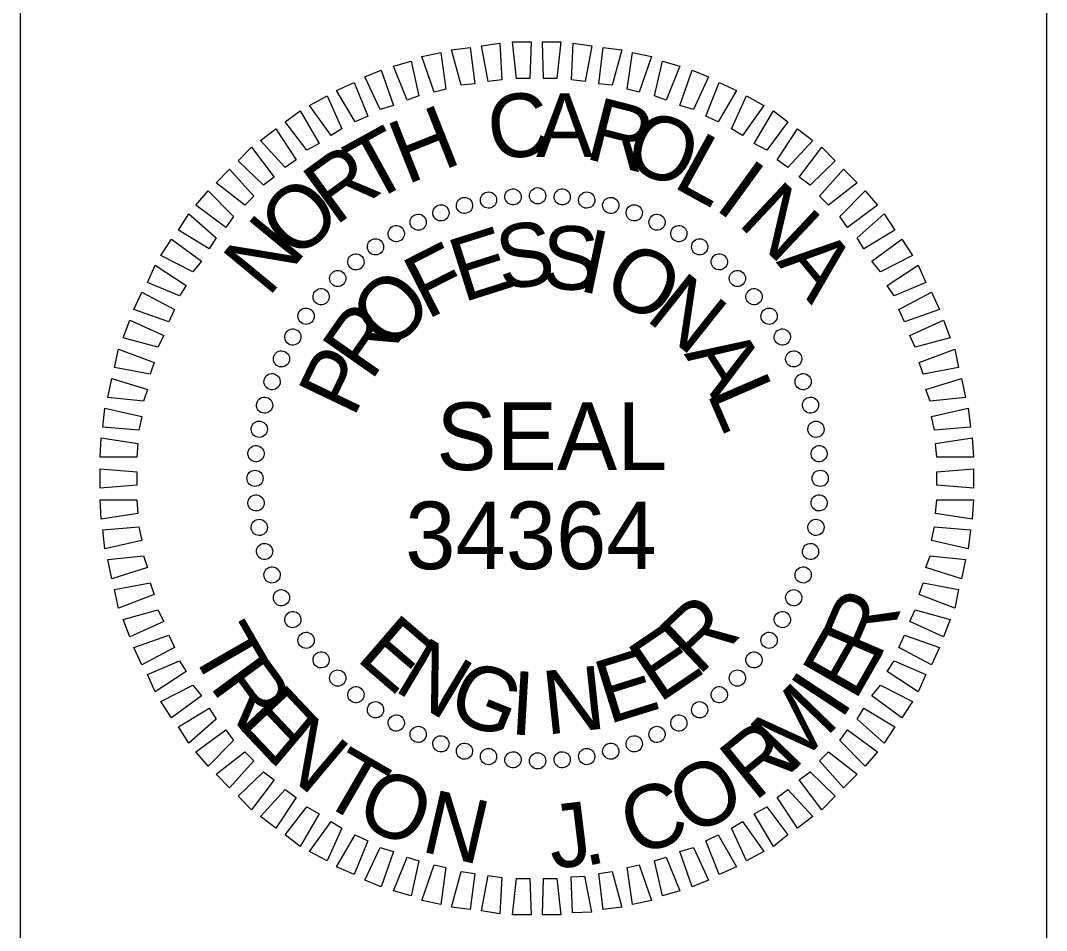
# Model space of a CAD drawing. Extents: x 2.6 to 3.27, y 0.03 to 1.77.
# Drawn here: x 2.6042 to 2.7708, y 1.2034 to 1.3512 of the extents above; entities that cross this region are included whole.
import ezdxf

# ---------------------------------------------------------------- set-up
doc = ezdxf.new("R2010")
doc.units = 0
for name, color, linetype in [('Draft_RDY_Construction_Class_Element', 7, 'Continuous'), ('Old_Level_2', 7, 'Continuous'), ('Sheet_Plan_CELL', 7, 'Continuous')]:
    doc.layers.add(name, color=color, linetype=linetype)

msp = doc.modelspace()

# ---------------------------------------------------------------- linework, layer by layer
at = {"layer": 'Draft_RDY_Construction_Class_Element'}
for p, q in [((2.60416, 0.0625), (2.60416, 1.77083)), ((2.77078, 1.77083), (2.77078, 0.0625))]:
    msp.add_line(p, q, dxfattribs=at)
at = {"layer": 'Old_Level_2'}
for p, q in [((2.68002, 1.32201), (2.68002, 1.32201)), ((2.68397, 1.32256), (2.68397, 1.32256)), ((2.68799, 1.32276), (2.68799, 1.32276)), ((2.69202, 1.32256), (2.69202, 1.32256)), ((2.69595, 1.32201), (2.69595, 1.32201)), ((2.67225, 1.32001), (2.67225, 1.32001)), ((2.67609, 1.32121), (2.67609, 1.32121)), ((2.69988, 1.32121), (2.69988, 1.32121)), ((2.70372, 1.32001), (2.70372, 1.32001)), ((2.66859, 1.31846), (2.66859, 1.31846)), ((2.7074, 1.31846), (2.7074, 1.31846)), ((2.66503, 1.3166), (2.66503, 1.3166)), ((2.71096, 1.3166), (2.71096, 1.3166)), ((2.66165, 1.31442), (2.66165, 1.31442)), ((2.71434, 1.31442), (2.71434, 1.31442)), ((2.65844, 1.31202), (2.65844, 1.31202)), ((2.71755, 1.31202), (2.71755, 1.31202)), ((2.6555, 1.30927), (2.6555, 1.30927)), ((2.72045, 1.30927), (2.72045, 1.30927)), ((2.65275, 1.30637), (2.65275, 1.30637)), ((2.7232, 1.30637), (2.7232, 1.30637)), ((2.65037, 1.30316), (2.65037, 1.30316)), ((2.7256, 1.30316), (2.7256, 1.30316)), ((2.64819, 1.29978), (2.64819, 1.29978)), ((2.72778, 1.29978), (2.72778, 1.29978)), ((2.64636, 1.2962), (2.64636, 1.2962)), ((2.72964, 1.2962), (2.72964, 1.2962)), ((2.64481, 1.29254), (2.64481, 1.29254)), ((2.73119, 1.29254), (2.73119, 1.29254)), ((2.64361, 1.2887), (2.64361, 1.2887)), ((2.73239, 1.2887), (2.73239, 1.2887)), ((2.64278, 1.28477), (2.64278, 1.28477)), ((2.73319, 1.28477), (2.73319, 1.28477)), ((2.64223, 1.28084), (2.64223, 1.28084)), ((2.73374, 1.28084), (2.73374, 1.28084)), ((2.64206, 1.27681), (2.64206, 1.27681)), ((2.73393, 1.27681), (2.73393, 1.27681)), ((2.64223, 1.27279), (2.64223, 1.27279)), ((2.73374, 1.27279), (2.73374, 1.27279)), ((2.64278, 1.26884), (2.64278, 1.26884)), ((2.73319, 1.26884), (2.73319, 1.26884)), ((2.64361, 1.26492), (2.64361, 1.26492)), ((2.73239, 1.26492), (2.73239, 1.26492)), ((2.64481, 1.26108), (2.64481, 1.26108)), ((2.73119, 1.26108), (2.73119, 1.26108)), ((2.64636, 1.25741), (2.64636, 1.25741)), ((2.72964, 1.25741), (2.72964, 1.25741)), ((2.64819, 1.25383), (2.64819, 1.25383)), ((2.72778, 1.25383), (2.72778, 1.25383)), ((2.65037, 1.25047), (2.65037, 1.25047)), ((2.7256, 1.25047), (2.7256, 1.25047)), ((2.65275, 1.24727), (2.65275, 1.24727)), ((2.7232, 1.24727), (2.7232, 1.24727)), ((2.6555, 1.24432), (2.6555, 1.24432)), ((2.72045, 1.24432), (2.72045, 1.24432)), ((2.65844, 1.24157), (2.65844, 1.24157)), ((2.71755, 1.24157), (2.71755, 1.24157)), ((2.66165, 1.23919), (2.66165, 1.23919)), ((2.71434, 1.23919), (2.71434, 1.23919)), ((2.66503, 1.23699), (2.66503, 1.23699)), ((2.71096, 1.23699), (2.71096, 1.23699)), ((2.66859, 1.23518), (2.66859, 1.23518)), ((2.7074, 1.23518), (2.7074, 1.23518)), ((2.67225, 1.23363), (2.67225, 1.23363)), ((2.70372, 1.23363), (2.70372, 1.23363)), ((2.67609, 1.23243), (2.67609, 1.23243)), ((2.68002, 1.2316), (2.68002, 1.2316)), ((2.69595, 1.2316), (2.69595, 1.2316)), ((2.69988, 1.23243), (2.69988, 1.23243)), ((2.68397, 1.23105), (2.68397, 1.23105)), ((2.68799, 1.23088), (2.68799, 1.23088)), ((2.69202, 1.23105), (2.69202, 1.23105))]:
    msp.add_line(p, q, dxfattribs=at)
for points in [[(2.67572, 1.34069), (2.67417, 1.34645), (2.67719, 1.3468), (2.67793, 1.34095)], [(2.68013, 1.3413), (2.67902, 1.34708), (2.68203, 1.34754), (2.68231, 1.34159)], [(2.68469, 1.34178), (2.68406, 1.34774), (2.68707, 1.34774), (2.68689, 1.34178)], [(2.68908, 1.34178), (2.68892, 1.34774), (2.69191, 1.34774), (2.69128, 1.34178)], [(2.69366, 1.34159), (2.69392, 1.34754), (2.69695, 1.34708), (2.69586, 1.3413)], [(2.69807, 1.34095), (2.69879, 1.3468), (2.70182, 1.34645), (2.70025, 1.34069)], [(2.67134, 1.33958), (2.66933, 1.34534), (2.67243, 1.34599), (2.67326, 1.34004)], [(2.70271, 1.34004), (2.70356, 1.34599), (2.70666, 1.34534), (2.70465, 1.33958)], [(2.66255, 1.33674), (2.66008, 1.34204), (2.66274, 1.34313), (2.66475, 1.3374)], [(2.66695, 1.33829), (2.66475, 1.34379), (2.66759, 1.3446), (2.66885, 1.33895)], [(2.70712, 1.33895), (2.70841, 1.3446), (2.71122, 1.34379), (2.70904, 1.33829)], [(2.71122, 1.3374), (2.71325, 1.34313), (2.71589, 1.34204), (2.71343, 1.33674)], [(2.65851, 1.33473), (2.6555, 1.33984), (2.65836, 1.34115), (2.66054, 1.33565)], [(2.71545, 1.33565), (2.71764, 1.34115), (2.72045, 1.33984), (2.71746, 1.33473)], [(2.6546, 1.33255), (2.65111, 1.3374), (2.65395, 1.33895), (2.65635, 1.33364)], [(2.71964, 1.33364), (2.72204, 1.33895), (2.72486, 1.3374), (2.72139, 1.33255)], [(2.65065, 1.33015), (2.64716, 1.33473), (2.64956, 1.33655), (2.65266, 1.33124)], [(2.72331, 1.33124), (2.72643, 1.33655), (2.72879, 1.33473), (2.72534, 1.33015)], [(2.64716, 1.32732), (2.64315, 1.3317), (2.64561, 1.33364), (2.64891, 1.3286)], [(2.72706, 1.3286), (2.73036, 1.33364), (2.73282, 1.3317), (2.72879, 1.32732)], [(2.64361, 1.32448), (2.63951, 1.32841), (2.64169, 1.33061), (2.64535, 1.32577)], [(2.73064, 1.32577), (2.73428, 1.33061), (2.73649, 1.32841), (2.73239, 1.32448)], [(2.6406, 1.32121), (2.63593, 1.32485), (2.63811, 1.32705), (2.64206, 1.32265)], [(2.73393, 1.32265), (2.73784, 1.32705), (2.74004, 1.32485), (2.7354, 1.32121)], [(2.63748, 1.31761), (2.63263, 1.32121), (2.63464, 1.32356), (2.63876, 1.31935)], [(2.73723, 1.31935), (2.74133, 1.32356), (2.74334, 1.32121), (2.73849, 1.31761)], [(2.63481, 1.31414), (2.6298, 1.31717), (2.63152, 1.31981), (2.63593, 1.31588)], [(2.74004, 1.31588), (2.74443, 1.31981), (2.74617, 1.31717), (2.74113, 1.31414)], [(2.63217, 1.31039), (2.62696, 1.31303), (2.62868, 1.31571), (2.63353, 1.31213)], [(2.74242, 1.31213), (2.74729, 1.31571), (2.74903, 1.31303), (2.74382, 1.31039)], [(2.62997, 1.30646), (2.62478, 1.30866), (2.62604, 1.31148), (2.63108, 1.30818)], [(2.74491, 1.30818), (2.74993, 1.31148), (2.75121, 1.30866), (2.74602, 1.30646)], [(2.62823, 1.30225), (2.62257, 1.30428), (2.62384, 1.30709), (2.62916, 1.30428)], [(2.74683, 1.30428), (2.75213, 1.30709), (2.75342, 1.30428), (2.74772, 1.30225)], [(2.62648, 1.29812), (2.62083, 1.29967), (2.62192, 1.30253), (2.62742, 1.30004)], [(2.74857, 1.30004), (2.75405, 1.30253), (2.75516, 1.29967), (2.74947, 1.29812)], [(2.62521, 1.29374), (2.61945, 1.29483), (2.62009, 1.29784), (2.62587, 1.29564)], [(2.75012, 1.29564), (2.75588, 1.29784), (2.75652, 1.29483), (2.75076, 1.29374)], [(2.62412, 1.28935), (2.61834, 1.28999), (2.619, 1.29308), (2.62478, 1.29127)], [(2.75121, 1.29127), (2.75697, 1.29308), (2.75763, 1.28999), (2.75187, 1.28935)], [(2.62338, 1.28468), (2.61753, 1.28514), (2.61788, 1.28824), (2.62384, 1.28689)], [(2.75213, 1.28689), (2.75807, 1.28824), (2.75846, 1.28514), (2.75259, 1.28468)], [(2.62303, 1.2803), (2.61708, 1.2803), (2.61725, 1.2834), (2.62323, 1.28248)], [(2.75276, 1.28248), (2.75872, 1.2834), (2.75892, 1.2803), (2.75296, 1.2803)], [(2.62303, 1.27572), (2.61708, 1.27526), (2.61708, 1.27836), (2.62303, 1.2779)], [(2.75296, 1.2779), (2.75892, 1.27836), (2.75892, 1.27526), (2.75296, 1.27572)], [(2.62323, 1.27113), (2.61725, 1.27022), (2.61708, 1.27334), (2.62303, 1.27334)], [(2.75296, 1.27334), (2.75892, 1.27334), (2.75872, 1.27022), (2.75276, 1.27113)], [(2.62384, 1.26675), (2.61788, 1.26537), (2.61753, 1.26849), (2.62338, 1.26895)], [(2.75259, 1.26895), (2.75846, 1.26849), (2.75807, 1.26537), (2.75213, 1.26675)], [(2.62478, 1.26236), (2.619, 1.26051), (2.61834, 1.26363), (2.62412, 1.26426)], [(2.75187, 1.26426), (2.75763, 1.26363), (2.75697, 1.26051), (2.75121, 1.26236)], [(2.62587, 1.25796), (2.62009, 1.25577), (2.61945, 1.25879), (2.62521, 1.25988)], [(2.75076, 1.25988), (2.75652, 1.25879), (2.75588, 1.25577), (2.75012, 1.25796)], [(2.62742, 1.25357), (2.62192, 1.25111), (2.62083, 1.25392), (2.62648, 1.25547)], [(2.74947, 1.25547), (2.75516, 1.25392), (2.75405, 1.25111), (2.74857, 1.25357)], [(2.62916, 1.24936), (2.62384, 1.24652), (2.62257, 1.24936), (2.62823, 1.25137)], [(2.74772, 1.25137), (2.75342, 1.24936), (2.75213, 1.24652), (2.74683, 1.24936)], [(2.63108, 1.24543), (2.62604, 1.24214), (2.62478, 1.24497), (2.62997, 1.24718)], [(2.74602, 1.24718), (2.75121, 1.24497), (2.74993, 1.24214), (2.74491, 1.24543)], [(2.63353, 1.24148), (2.62868, 1.23793), (2.62696, 1.24057), (2.63217, 1.24323)], [(2.74382, 1.24323), (2.74903, 1.24057), (2.74729, 1.23793), (2.74242, 1.24148)], [(2.63593, 1.23773), (2.63152, 1.2338), (2.6298, 1.23644), (2.63481, 1.23948)], [(2.74113, 1.23948), (2.74617, 1.23644), (2.74443, 1.2338), (2.74004, 1.23773)], [(2.63876, 1.23424), (2.63464, 1.23005), (2.63263, 1.23243), (2.63748, 1.23599)], [(2.73849, 1.23599), (2.74334, 1.23243), (2.74133, 1.23005), (2.73723, 1.23424)], [(2.64206, 1.23097), (2.63811, 1.22658), (2.63593, 1.22879), (2.6406, 1.23243)], [(2.7354, 1.23243), (2.74004, 1.22879), (2.73784, 1.22658), (2.73393, 1.23097)], [(2.64535, 1.22785), (2.64169, 1.223), (2.63951, 1.22521), (2.64361, 1.22913)], [(2.73239, 1.22913), (2.73649, 1.22521), (2.73428, 1.223), (2.73064, 1.22785)], [(2.64891, 1.22501), (2.64561, 1.21999), (2.64315, 1.22191), (2.64716, 1.2263)], [(2.72879, 1.2263), (2.73282, 1.22191), (2.73036, 1.21999), (2.72706, 1.22501)], [(2.65266, 1.22235), (2.64956, 1.21705), (2.64716, 1.2189), (2.65065, 1.22346)], [(2.72534, 1.22346), (2.72879, 1.2189), (2.72643, 1.21705), (2.72331, 1.22235)], [(2.65635, 1.21999), (2.65395, 1.21469), (2.65111, 1.21624), (2.6546, 1.22108)], [(2.72139, 1.22108), (2.72486, 1.21624), (2.72204, 1.21469), (2.71964, 1.21999)], [(2.66054, 1.21796), (2.65836, 1.21249), (2.6555, 1.21375), (2.65851, 1.2189)], [(2.71746, 1.2189), (2.72045, 1.21375), (2.71764, 1.21249), (2.71545, 1.21796)], [(2.66475, 1.21624), (2.66274, 1.21046), (2.66008, 1.21157), (2.66255, 1.21687)], [(2.71343, 1.21687), (2.71589, 1.21157), (2.71325, 1.21046), (2.71122, 1.21624)], [(2.66885, 1.21469), (2.66759, 1.209), (2.66475, 1.20983), (2.66695, 1.2153)], [(2.70904, 1.2153), (2.71122, 1.20983), (2.70841, 1.209), (2.70712, 1.21469)], [(2.67326, 1.2136), (2.67243, 1.20762), (2.66933, 1.20828), (2.67134, 1.21404)], [(2.70465, 1.21404), (2.70666, 1.20828), (2.70356, 1.20762), (2.70271, 1.2136)], [(2.67793, 1.21266), (2.67719, 1.20681), (2.67417, 1.20716), (2.67572, 1.21295)], [(2.68231, 1.21201), (2.68203, 1.20607), (2.67902, 1.20655), (2.68013, 1.21231)], [(2.68689, 1.21185), (2.68707, 1.2059), (2.68406, 1.2059), (2.68469, 1.21185)], [(2.69128, 1.21185), (2.69191, 1.2059), (2.68892, 1.2059), (2.68908, 1.21185)], [(2.69577, 1.2122), (2.69687, 1.20636), (2.69383, 1.20627), (2.69357, 1.21212)], [(2.70025, 1.21295), (2.70182, 1.20716), (2.69879, 1.20681), (2.69807, 1.21266)]]:
    msp.add_lwpolyline(points, close=True, dxfattribs=at)
for centre, major_axis in [((2.68017, 1.32204), (-0.00023, 0.0013)), ((2.68414, 1.32256), (-0.00011, 0.00131)), ((2.68814, 1.32274), (0, 0.00132)), ((2.69214, 1.32256), (0.00011, 0.00131)), ((2.69611, 1.32204), (0.00023, 0.0013)), ((2.67244, 1.31997), (-0.00045, 0.00124)), ((2.67626, 1.32117), (-0.00034, 0.00127)), ((2.70001, 1.32117), (0.00034, 0.00127)), ((2.70383, 1.31997), (0.00045, 0.00124)), ((2.66874, 1.31844), (-0.00056, 0.00119)), ((2.70753, 1.31844), (0.00056, 0.00119)), ((2.66519, 1.31659), (-0.00066, 0.00114)), ((2.71108, 1.31659), (0.00066, 0.00114)), ((2.66181, 1.31444), (-0.00076, 0.00108)), ((2.71446, 1.31444), (0.00076, 0.00108)), ((2.65863, 1.312), (-0.00085, 0.00101)), ((2.71764, 1.312), (0.00085, 0.00101)), ((2.65568, 1.3093), (-0.000932, 0.000932)), ((2.72059, 1.3093), (0.000932, 0.000932)), ((2.65298, 1.30634), (-0.00101, 0.00085)), ((2.72329, 1.30634), (0.00101, 0.00085)), ((2.65054, 1.30317), (-0.00108, 0.00076)), ((2.72573, 1.30317), (0.00108, 0.00076)), ((2.64839, 1.29979), (-0.00114, 0.00066)), ((2.72788, 1.29979), (0.00114, 0.00066)), ((2.64654, 1.29624), (-0.00119, 0.00056)), ((2.72973, 1.29624), (0.00119, 0.00056)), ((2.64501, 1.29254), (-0.00124, 0.00045)), ((2.73126, 1.29254), (0.00124, 0.00045)), ((2.6438, 1.28872), (-0.00127, 0.00034)), ((2.73247, 1.28872), (0.00127, 0.00034)), ((2.64294, 1.28481), (-0.0013, 0.00023)), ((2.73334, 1.28481), (0.0013, 0.00023)), ((2.64241, 1.28084), (-0.00131, 0.00011)), ((2.73386, 1.28084), (0.00131, 0.00011)), ((2.64224, 1.27684), (-0.00132, 0)), ((2.73403, 1.27684), (0.00132, 0)), ((2.64241, 1.27284), (-0.00131, -0.00011)), ((2.73386, 1.27284), (0.00131, -0.00011)), ((2.64294, 1.26887), (-0.0013, -0.00023)), ((2.73334, 1.26887), (0.0013, -0.00023)), ((2.6438, 1.26496), (-0.00127, -0.00034)), ((2.73247, 1.26496), (0.00127, -0.00034)), ((2.64501, 1.26114), (-0.00124, -0.00045)), ((2.73126, 1.26114), (0.00124, -0.00045)), ((2.64654, 1.25744), (-0.00119, -0.00056)), ((2.72973, 1.25744), (0.00119, -0.00056)), ((2.64839, 1.25389), (-0.00114, -0.00066)), ((2.72788, 1.25389), (0.00114, -0.00066)), ((2.65054, 1.25052), (-0.00108, -0.00076)), ((2.72573, 1.25052), (0.00108, -0.00076)), ((2.65298, 1.24734), (-0.00101, -0.00085)), ((2.72329, 1.24734), (0.00101, -0.00085)), ((2.65568, 1.24439), (-0.000932, -0.000932)), ((2.72059, 1.24439), (0.000932, -0.000932)), ((2.65863, 1.24168), (-0.00085, -0.00101)), ((2.71764, 1.24168), (0.00085, -0.00101)), ((2.66181, 1.23924), (-0.00076, -0.00108)), ((2.71446, 1.23924), (0.00076, -0.00108)), ((2.66519, 1.23709), (-0.00066, -0.00114)), ((2.71108, 1.23709), (0.00066, -0.00114)), ((2.66874, 1.23524), (-0.00056, -0.00119)), ((2.70753, 1.23524), (0.00056, -0.00119)), ((2.67244, 1.23371), (-0.00045, -0.00124)), ((2.70383, 1.23371), (0.00045, -0.00124)), ((2.67626, 1.23251), (-0.00034, -0.00127)), ((2.68017, 1.23164), (-0.00023, -0.0013)), ((2.69611, 1.23164), (0.00023, -0.0013)), ((2.70001, 1.23251), (0.00034, -0.00127)), ((2.68414, 1.23112), (-0.00011, -0.00131)), ((2.68814, 1.23094), (0, -0.00132)), ((2.69214, 1.23112), (0.00011, -0.00131))]:
    msp.add_ellipse(centre, major_axis=major_axis, ratio=0.999708, dxfattribs=at)
at = {"layer": 'Sheet_Plan_CELL'}
msp.add_circle((2.68751, 1.28357), 0.0001, dxfattribs=at)

# ---------------------------------------------------------------- texts
at = {"layer": 'Old_Level_2'}
for s, height, rotation, p in [('C', 0.01032, 7.2199, (2.68068, 1.32841)), ('A', 0.01032, 0.0203, (2.6879, 1.32906)), ('R', 0.01032, 345.6211, (2.69558, 1.32887)), ('H', 0.01032, 21.6195, (2.66684, 1.32448)), ('O', 0.01032, 338.4212, (2.70171, 1.3276)), ('T', 0.01032, 28.8198, (2.66091, 1.32136)), ('L', 0.01032, 331.2209, (2.70985, 1.32431)), ('R', 0.01032, 36.0205, (2.65524, 1.31772)), ('I', 0.01032, 324.0201, (2.71663, 1.32073)), ('O', 0.01032, 43.2217, (2.64902, 1.31196)), ('N', 0.01032, 316.8189, (2.72045, 1.31817)), ('N', 0.01032, 50.4235, (2.64441, 1.30609)), ('S', 0.01032, 8.2556, (2.68223, 1.30737)), ('S', 0.01032, 358.9004, (2.68881, 1.30757)), ('E', 0.01032, 17.6111, (2.67599, 1.30537)), ('I', 0.01032, 348.1506, (2.69449, 1.30737)), ('F', 0.01032, 26.967, (2.67014, 1.30253)), ('A', 0.01032, 309.6172, (2.72678, 1.31196)), ('O', 0.01032, 330.8335, (2.69822, 1.30692)), ('O', 0.01032, 45.6812, (2.6642, 1.29703)), ('N', 0.01032, 321.4766, (2.70546, 1.30271)), ('R', 0.01032, 55.0397, (2.66108, 1.29245)), ('A', 0.01032, 302.7603, (2.71185, 1.29703)), ('P', 0.01032, 64.3989, (2.65825, 1.28649)), ('L', 0.01032, 293.4009, (2.71554, 1.29073)), ('R', 0.01034, 66.8673, (2.74343, 1.24666)), ('R', 0.01032, 43.4814, (2.71425, 1.24458)), ('T', 0.01034, 300.0126, (2.63142, 1.24919)), ('E', 0.01032, 319.2769, (2.65844, 1.24744)), ('E', 0.01032, 34.1241, (2.70786, 1.24022)), ('E', 0.01034, 60.2514, (2.73969, 1.24047)), ('N', 0.01032, 329.1641, (2.66455, 1.24249)), ('R', 0.01034, 306.3408, (2.63471, 1.24311)), ('E', 0.01032, 17.2883, (2.69961, 1.23684)), ('G', 0.01032, 337.9902, (2.673, 1.23828)), ('N', 0.01032, 6.0564, (2.68953, 1.23518)), ('I', 0.01032, 356.7012, (2.68351, 1.23527)), ('I', 0.01034, 56.7134, (2.7374, 1.23736)), ('E', 0.01034, 313.3019, (2.63908, 1.23689)), ('M', 0.01034, 45.9842, (2.72936, 1.22884)), ('N', 0.01034, 319.9177, (2.64391, 1.23151)), ('R', 0.01034, 39.0232, (2.72335, 1.22419)), ('T', 0.01034, 329.899, (2.65228, 1.22453)), ('O', 0.01034, 28.2652, (2.71307, 1.21851)), ('O', 0.01034, 336.2272, (2.65816, 1.2209)), ('C', 0.01034, 19.3482, (2.70386, 1.21533)), ('N', 0.01034, 346.9852, (2.66896, 1.21628)), ('J', 0.01034, 6.9478, (2.69048, 1.21335)), ('.', 0.01034, 11.8407, (2.69581, 1.21378))]:
    msp.add_text(s, height=height, rotation=rotation, dxfattribs=at).set_placement(p)
for s, height, p in [('SEAL', 0.010977, (2.67169, 1.27818)), ('34364', 0.01098, (2.66664, 1.26208))]:
    msp.add_text(s, height=height, dxfattribs=at).set_placement(p)

doc.saveas('drawing.dxf')
